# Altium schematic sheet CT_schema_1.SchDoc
size 534 x 506 mm
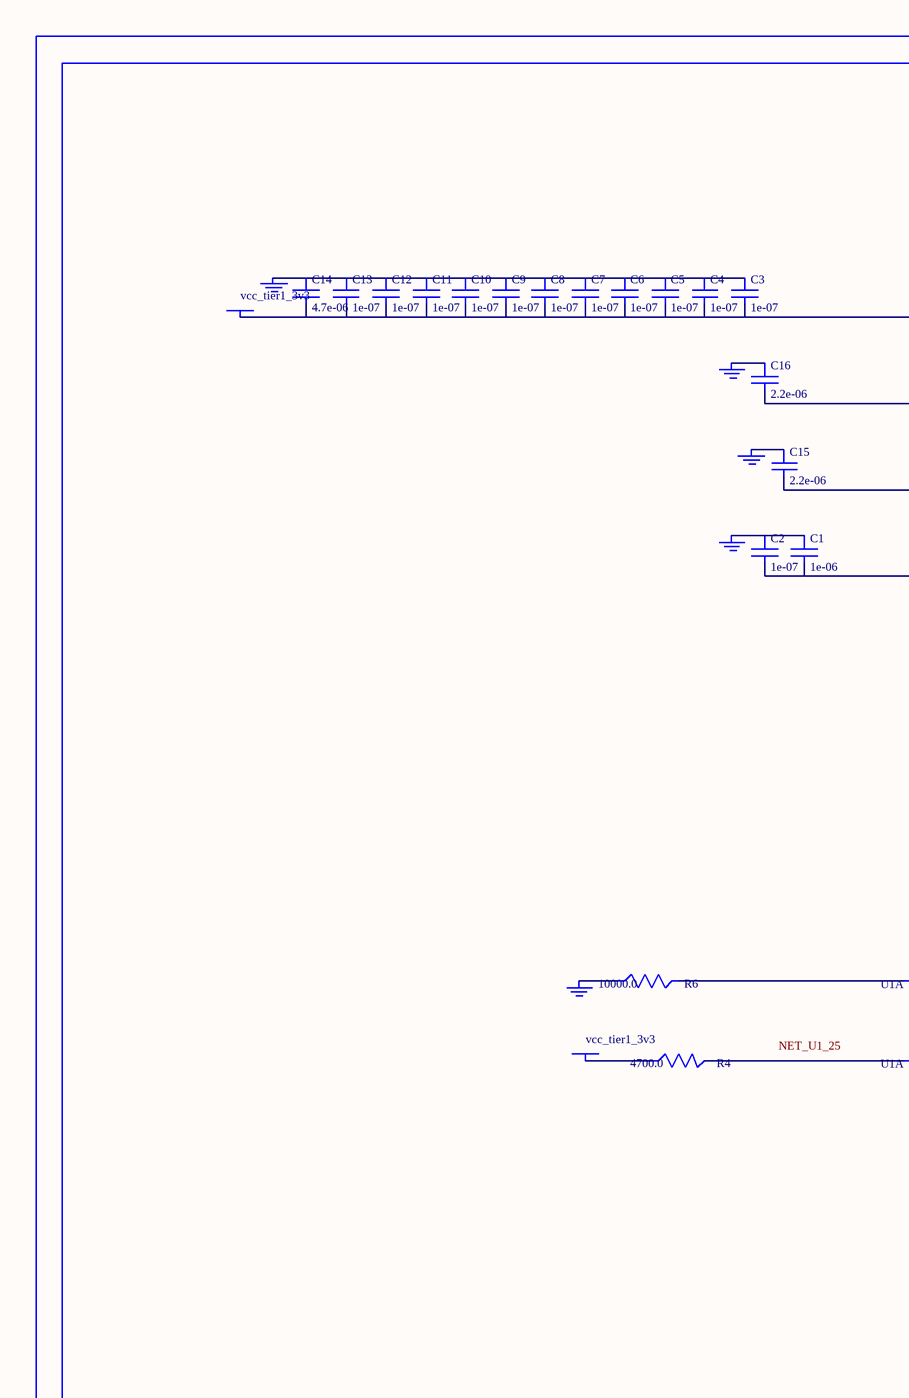
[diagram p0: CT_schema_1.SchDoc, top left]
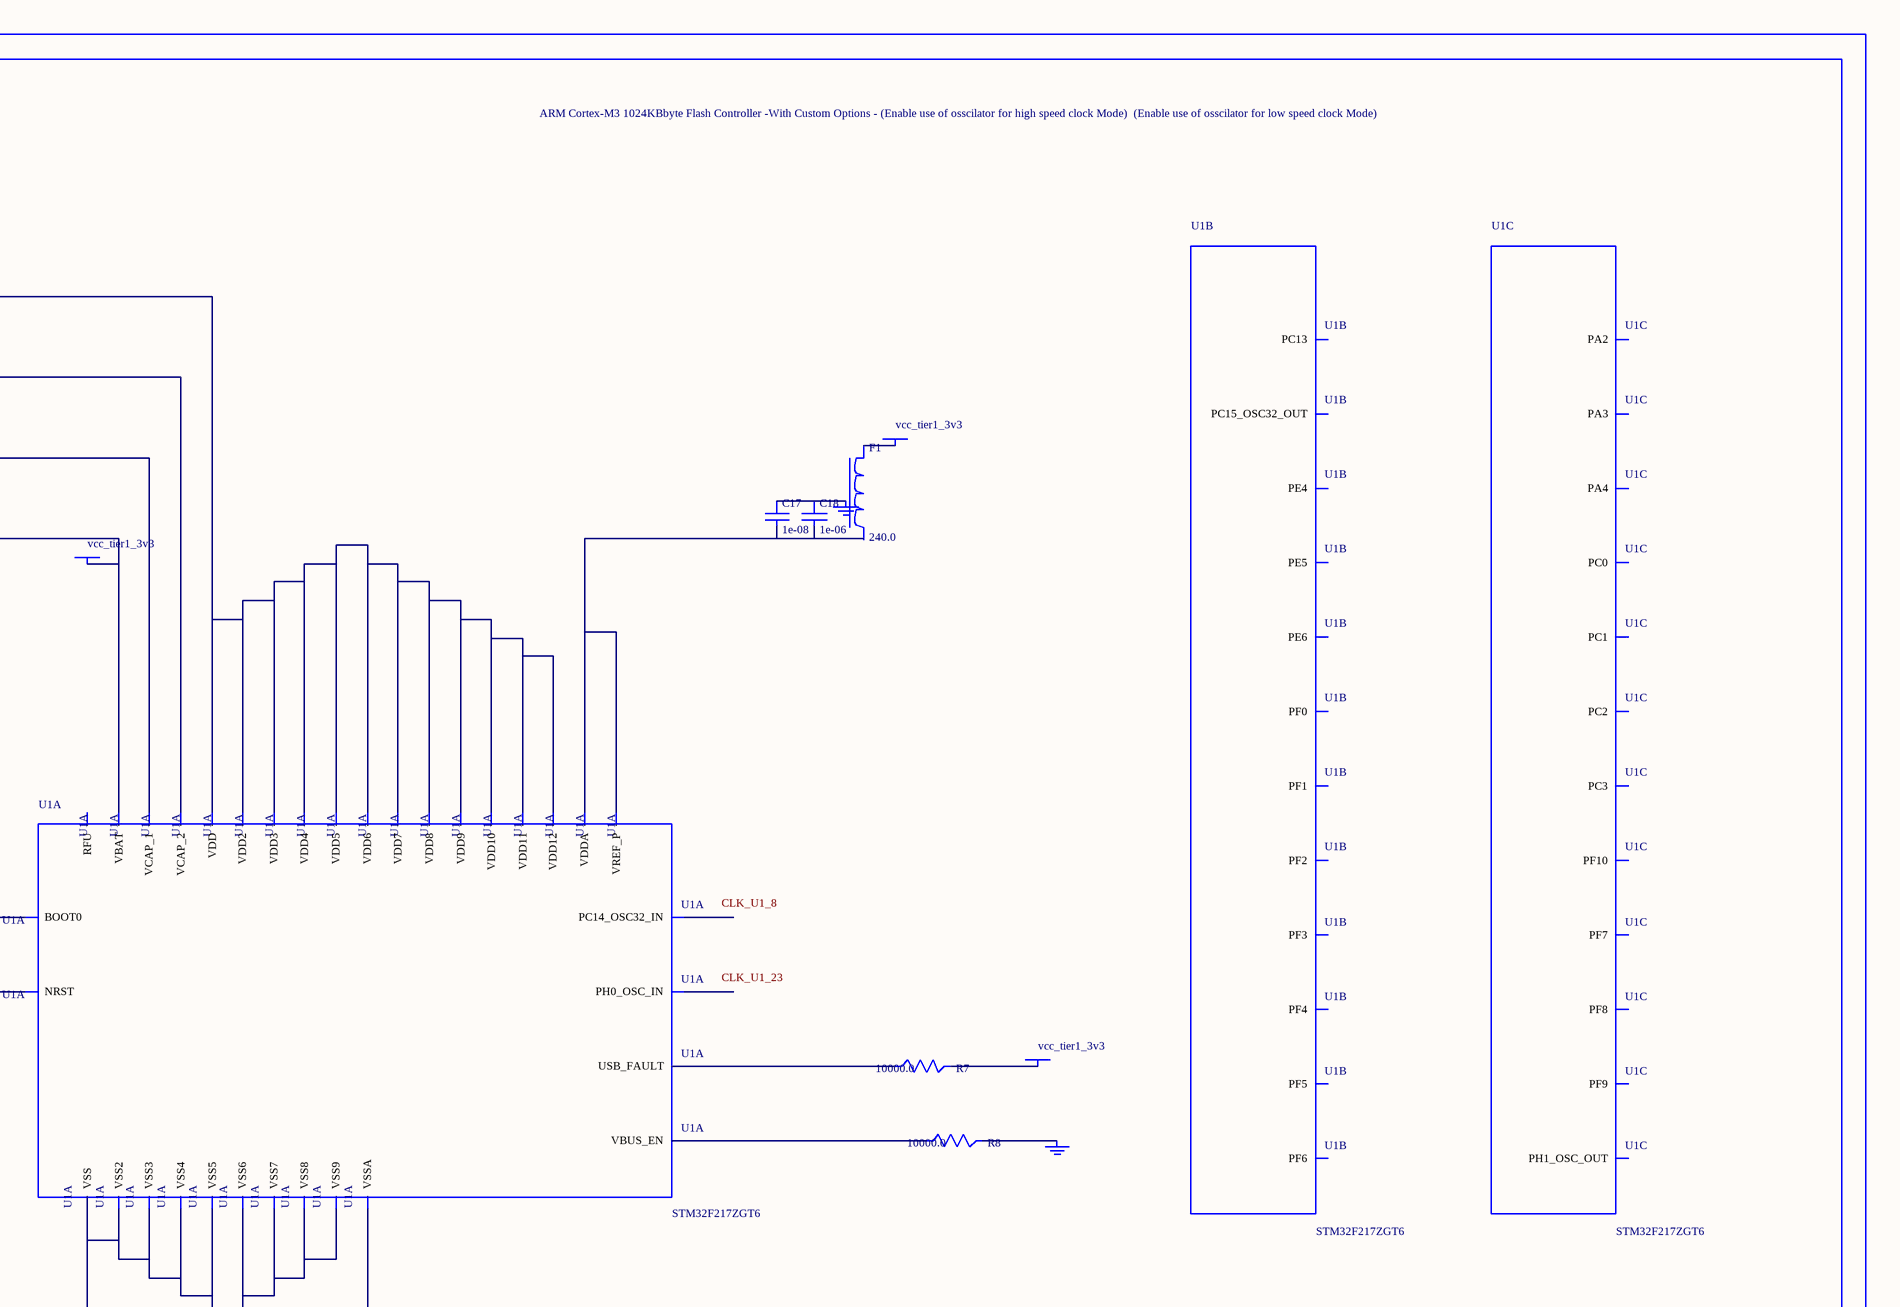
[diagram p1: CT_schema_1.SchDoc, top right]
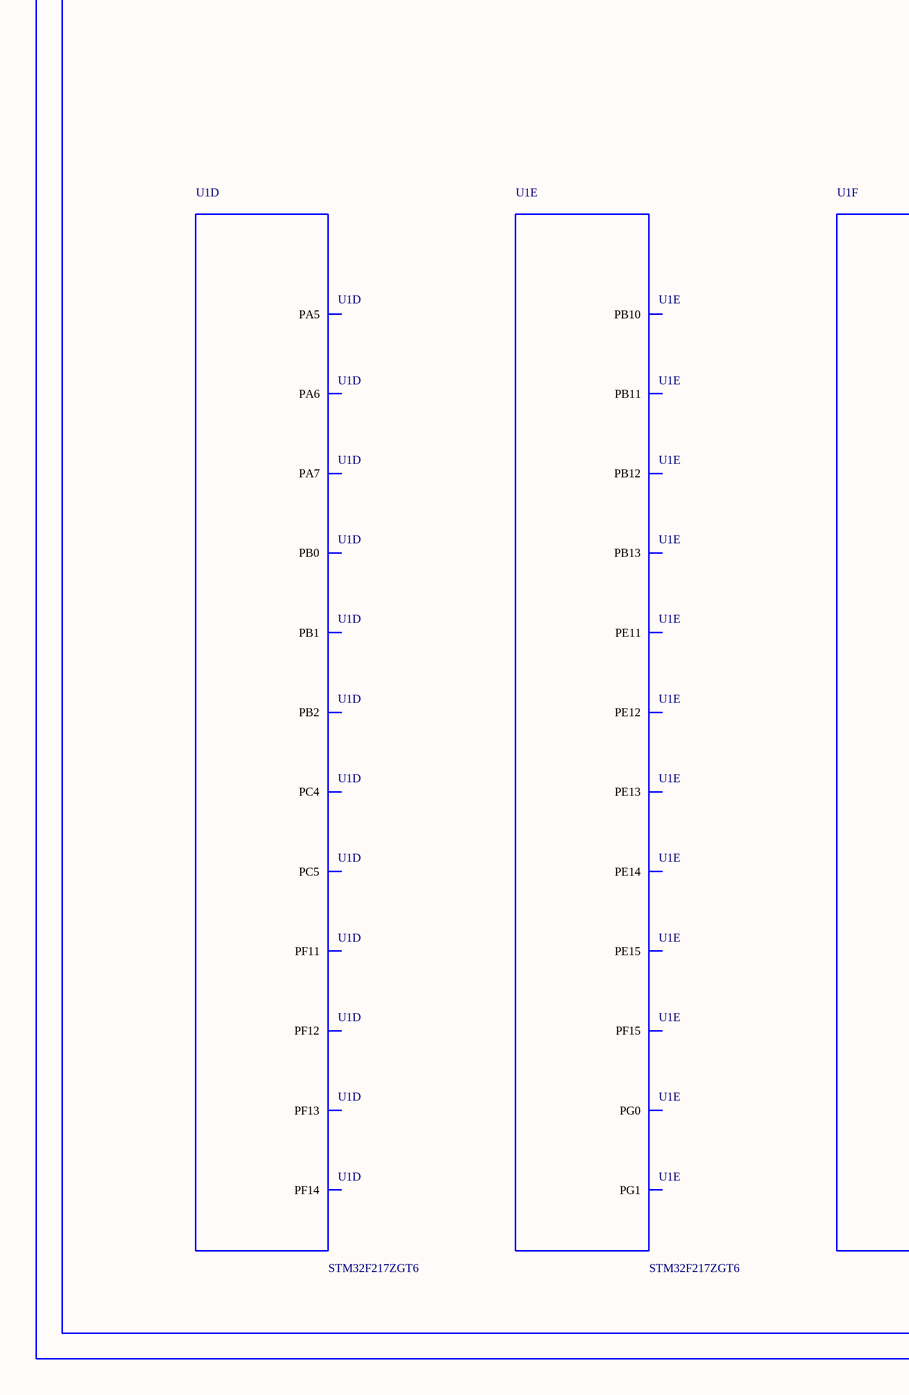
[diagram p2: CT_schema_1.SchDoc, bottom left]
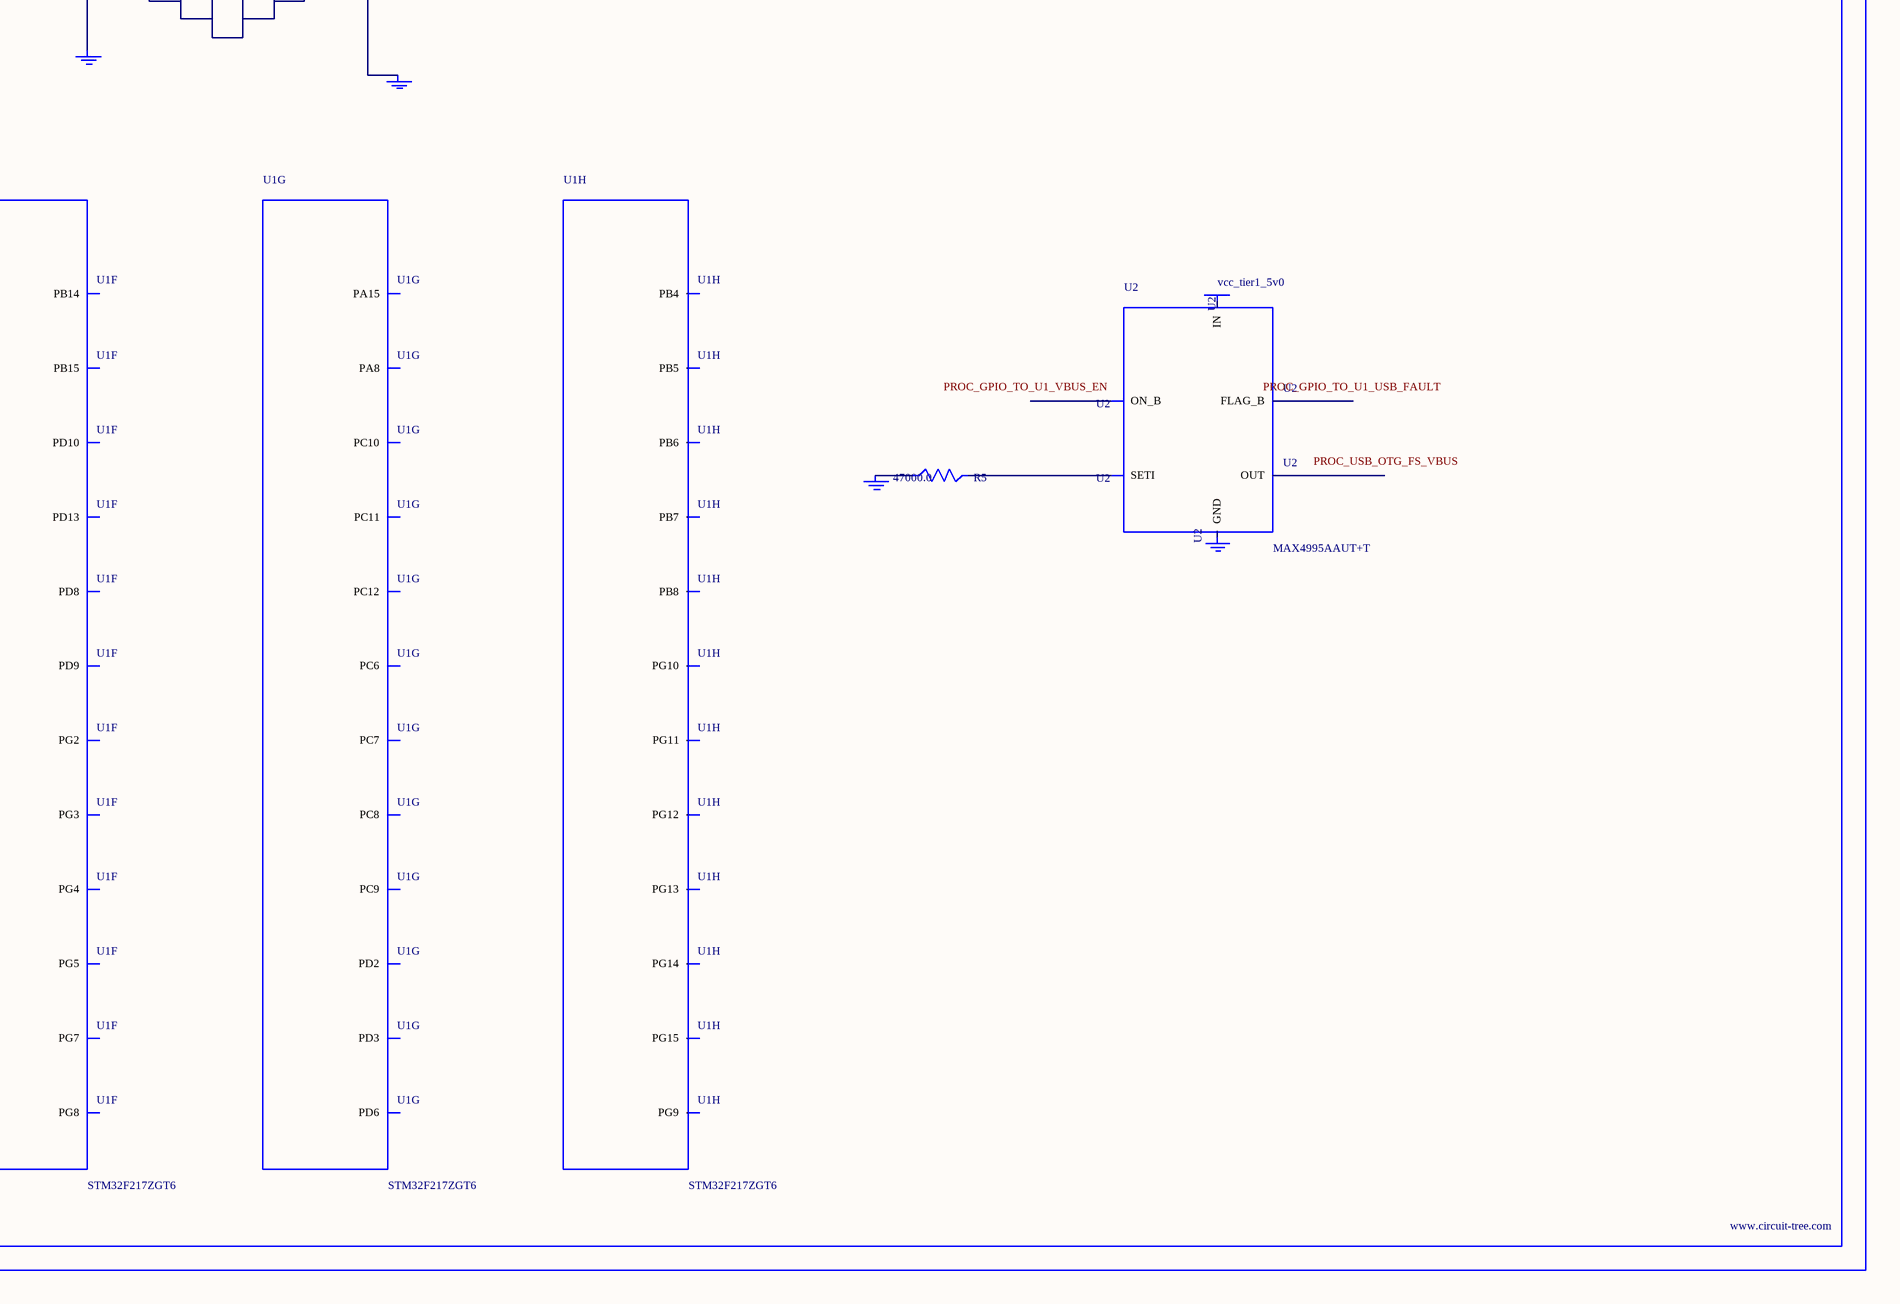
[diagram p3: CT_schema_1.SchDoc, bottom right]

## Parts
BORDER0  (no value)
C1  1e-06  [C0603]
C2  1e-07  [C0603]
C3  1e-07  [C0603]
C4  1e-07  [C0603]
C5  1e-07  [C0603]
C6  1e-07  [C0603]
C7  1e-07  [C0603]
C8  1e-07  [C0603]
C9  1e-07  [C0603]
C10  1e-07  [C0603]
C11  1e-07  [C0603]
C12  1e-07  [C0603]
C13  1e-07  [C0603]
C14  4.7e-06  [C0603]
C15  2.2e-06  [C0603]
C16  2.2e-06  [C0603]
C17  1e-08  [C0603]
C18  1e-06  [C0603]
F1  240.0  [L0603]
GND_INSTANCE_0_0  (no value)
GND_INSTANCE_0_1  (no value)
GND_INSTANCE_0_2  (no value)
GND_INSTANCE_0_3  (no value)
GND_INSTANCE_0_4  (no value)
GND_INSTANCE_0_5  (no value)
GND_INSTANCE_0_6  (no value)
GND_INSTANCE_0_7  (no value)
GND_INSTANCE_0_8  (no value)
GND_INSTANCE_0_9  (no value)
GND_INSTANCE_0_10  (no value)
POWER_INSTANCE_0_0  vcc_tier1_3v3
POWER_INSTANCE_0_1  vcc_tier1_3v3
POWER_INSTANCE_0_2  vcc_tier1_3v3
POWER_INSTANCE_0_3  vcc_tier1_3v3
POWER_INSTANCE_0_4  vcc_tier1_3v3
POWER_INSTANCE_0_5  vcc_tier1_5v0
R4  4700.0  [R0603]
R5  47000.0  [R0603]
R6  10000.0  [R0603]
R7  10000.0  [R0603]
R8  10000.0  [R0603]
U1  STM32F217ZGT6  [LQFP144]  (parts A,B,C,D,E,F,G,H of 13)
U2  MAX4995AAUT+T  [SOT-23-6]

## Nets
NetC1_1: C1.1 C2.1 GND_INSTANCE_0_1.0(GND)
NetC1_2: C1.2 C2.2 POWER_INSTANCE_0_1.0(PWR) U1.6(VBAT)
NetC3_1: C3.1 C4.1 C5.1 C6.1 C7.1 C8.1 C9.1 C10.1 C11.1 C12.1 C13.1 C14.1 GND_INSTANCE_0_2.0(GND)
NetC3_2: C3.2 C4.2 C5.2 C6.2 C7.2 C8.2 C9.2 C10.2 C11.2 C12.2 C13.2 C14.2 POWER_INSTANCE_0_2.0(PWR) U1.17(VDD) U1.30(VDD2) U1.39(VDD3) U1.52(VDD4) U1.62(VDD5) U1.72(VDD6) U1.84(VDD7) U1.95(VDD8) U1.108(VDD9) U1.121(VDD10) U1.131(VDD11) U1.144(VDD12)
NetC15_1: C15.1 GND_INSTANCE_0_5.0(GND)
NetC15_2: C15.2 U1.71(VCAP_1)
NetC16_1: C16.1 GND_INSTANCE_0_6.0(GND)
NetC16_2: C16.2 U1.106(VCAP_2)
NetC17_1: C17.1 C18.1 GND_INSTANCE_0_4.0(GND)
NetC17_2: C17.2 C18.2 U1.32(VREF_P) U1.33(VDDA)
NetF1_1: F1.1 POWER_INSTANCE_0_3.0(PWR)
NetGND_INSTANCE_0_0_0: GND_INSTANCE_0_0.0(GND) R8.2
NetGND_INSTANCE_0_3_0: GND_INSTANCE_0_3.0(GND) U1.31(VSSA)
NetGND_INSTANCE_0_7_0: GND_INSTANCE_0_7.0(GND) R6.1
NetGND_INSTANCE_0_8_0: GND_INSTANCE_0_8.0(GND) U1.16(VSS) U1.38(VSS2) U1.51(VSS3) U1.61(VSS4) U1.83(VSS5) U1.94(VSS6) U1.107(VSS7) U1.120(VSS8) U1.130(VSS9)
NetGND_INSTANCE_0_9_0: GND_INSTANCE_0_9.0(GND) R5.1
NetPOWER_INSTANCE_0_0_0: POWER_INSTANCE_0_0.0(PWR) R7.2
NetPOWER_INSTANCE_0_4_0: POWER_INSTANCE_0_4.0(PWR) R4.1
NetR4_2: R4.2 U1.25(NRST)
NetR5_2: R5.2 U2.3(SETI)
NetR6_2: R6.2 U1.138(BOOT0)
NetR7_1: R7.1 U1.2(USB_FAULT)
NetR8_1: R8.1 U1.1(VBUS_EN)

Not connected (* = marked no-connect by the designer): F1 2; GND_INSTANCE_0_10 0(GND); POWER_INSTANCE_0_5 0(PWR); U1 3(PE4) 4(PE5) 5(PE6) 7(PC13) 8(PC14_OSC32_IN) 9(PC15_OSC32_OUT) 10(PF0) 11(PF1) 12(PF2) 13(PF3) 14(PF4) 15(PF5) 18(PF6) 19(PF7) 20(PF8) 21(PF9) 22(PF10) 23(PH0_OSC_IN) 24(PH1_OSC_OUT) 26(PC0) 27(PC1) 28(PC2) 29(PC3) 36(PA2) 37(PA3) 40(PA4) 41(PA5) 42(PA6) 43(PA7) 44(PC4) 45(PC5) 46(PB0) 47(PB1) 48(PB2) 49(PF11) 50(PF12) 53(PF13) 54(PF14) 55(PF15) 56(PG0) 57(PG1) 64(PE11) 65(PE12) 66(PE13) 67(PE14) 68(PE15) 69(PB10) 70(PB11) 73(PB12) 74(PB13) 75(PB14) 76(PB15) 77(PD8) 78(PD9) 79(PD10) 82(PD13) 87(PG2) 88(PG3) 89(PG4) 90(PG5) 92(PG7) 93(PG8) 96(PC6) 97(PC7) 98(PC8) 99(PC9) 100(PA8) 110(PA15) 111(PC10) 112(PC11) 113(PC12) 116(PD2) 117(PD3) 122(PD6) 124(PG9) 125(PG10) 126(PG11) 127(PG12) 128(PG13) 129(PG14) 132(PG15) 134(PB4) 135(PB5) 136(PB6) 137(PB7) 139(PB8) 143(RFU); U2 1(OUT) 2(GND) 4(ON_B) 5(IN) 6(FLAG_B)

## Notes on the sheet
- Labels drawn without touching a wire or pin: CLK_U1_8, CLK_U1_23, NET_U1_25, PROC_GPIO_TO_U1_USB_FAULT, PROC_GPIO_TO_U1_VBUS_EN, PROC_USB_OTG_FS_VBUS

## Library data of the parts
BORDER0 = BORDER_PAGE0
C1 C18 = C0603C105K3RACTU
C2-C13 = 06035C104K4Z2A
C14 = GRM188R6YA475KE15D
C15 C16 = C0603C225K8RACTU
C17 = 06035C103K4Z2A
F1 = Z0603C241ASMST
GND_INSTANCE_0_0-GND_INSTANCE_0_10 = GND
POWER_INSTANCE_0_0-POWER_INSTANCE_0_5 = PWR
R4 = RC0603JR-074K7L
R5 = RC0603JR-0747KL
R6-R8 = RC0603JR-0710KL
